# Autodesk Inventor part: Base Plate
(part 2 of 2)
node "Face6"
  sketch "Sketch28"
    geometry: L1 (-175.545, 291.309)-(-196.287, 260.747) reference; L2 (304.8, 342.9)-(304.8, 127) reference; L3 (-192.1, 280.581)-(-182.826, 280.581); L4 (-197.815, 271.464)-(-194.15, 263.894); L5 (-194.15, 263.894)-(-182.826, 280.581); L6 (-175.545, 123.828)-(-196.287, 93.265) reference; L7 (-118.712, 207.569)-(-139.454, 177.006) reference; L8 (-139.454, 241.697)-(-118.712, 211.135) reference; L9 (-118.712, 291.309)-(-139.454, 260.747) reference; L10 (-173.125, 135.136)-(-193.867, 165.698) reference; L11 (-193.867, 169.264)-(-173.125, 199.827) reference; L12 (-116.292, 135.136)-(-137.034, 165.698) reference; L13 (-137.034, 253.005)-(-116.292, 283.567) reference; L14 (-116.292, 302.617)-(-131.042, 324.351) reference; L15 (-128.415, 329.309)-(-98.915, 329.309) reference; L16 (-123.52, 313.267)-(-126.895, 318.24); L17 (-121.187, 276.355)-(-123.686, 265.644); L18 (-126.789, 279.408)-(-134.435, 271.502); L19 (-138.238, 262.538)-(-135.85, 269.224); L20 (-133.827, 257.73)-(-126.85, 261.501); L21 (-138.238, 262.538)-(-133.827, 257.73); L22 (-121.187, 276.355)-(-126.789, 279.408); L23 (-192.094, 211.118)-(-175.545, 211.135); L24 (-175.545, 211.135)-(-198.45, 244.885); L25 (-135.585, 213.092)-(-129.113, 226.46); L26 (-131.955, 204.327)-(-123.02, 201.221); L27 (-129.113, 226.46)-(-118.712, 211.135); L28 (-118.712, 207.569)-(-123.02, 201.221); L29 (-185.881, 161.988)-(-183.496, 150.417); L30 (-188.534, 165.96)-(-193.72, 169.48); L31 (-123.566, 154.323)-(-122.322, 144.02); L32 (-126.832, 159.138)-(-135.956, 164.11); L33 (-192.193, 110.292)-(-184.656, 110.402); L34 (116.292, 116.086)-(136.897, 85.725) reference; L35 (-193.867, 165.698)-(-183.496, 150.417); L36 (-196.287, 241.697)-(-175.545, 211.135) reference; L37 (-197.815, 220.236)-(-191.114, 234.076); L38 (-201.541, 93.265)-(-222.283, 123.828) reference; L39 (-203.543, 96.215)-(-201.541, 93.265); L40 (-196.287, 93.265)-(-184.656, 110.402); L41 (-123.52, 329.309)-(-123.52, 323.85); L42 (-197.815, 101.176)-(-194.944, 95.245); L43 (-123.52, 329.309)-(-126.626, 329.309); C1 r 1.905 at (-192.1, 274.231) reference; C2 r 1.905 at (-129.87, 323.85) reference; C3 r 1.905 at (-129.87, 267.087) reference; C4 r 1.905 at (-192.1, 217.468) reference; C5 r 1.905 at (-129.87, 210.325) reference; C6 r 1.905 at (-192.1, 160.706) reference; C7 r 1.905 at (-129.87, 153.562) reference; C8 r 1.905 at (-192.1, 103.943) reference; A1 r 6.35 centre (-129.87, 323.85) between (-126.895, 318.24) and (-123.52, 323.85); A2 r 6.35 centre (-192.1, 274.231) between (-192.1, 280.581) and (-197.815, 271.464); A3 r 3.175 centre (-178.172, 209.352) between (-175.545, 207.569) and (-175.545, 211.135) reference; A4 r 3.175 centre (-121.339, 209.352) between (-118.712, 207.569) and (-118.712, 211.135) reference; A5 r 6.35 centre (-129.87, 267.087) between (-123.686, 265.644) and (-134.435, 271.502); A6 r 6.35 centre (-192.1, 217.468) between (-198.45, 217.468) and (-192.094, 211.118); A7 r 6.35 centre (-129.87, 210.325) between (-135.585, 213.092) and (-131.955, 204.327); A8 r 3.175 centre (-121.339, 209.352) between (-118.712, 207.569) and (-118.712, 211.135); A9 r 6.35 centre (-192.1, 160.706) between (-185.881, 161.988) and (-188.534, 165.96); A10 r 6.35 centre (-129.87, 153.562) between (-123.566, 154.323) and (-126.832, 159.138); A11 r 6.35 centre (-192.1, 103.943) between (-198.098, 106.028) and (-192.193, 110.292); A12 r 3.175 centre (-191.239, 167.481) between (-193.867, 169.264) and (-193.867, 165.698) reference; A13 r 3.19 centre (-191.227, 167.49) between (-193.72, 169.48) and (-193.867, 165.698); A14 r 3.175 centre (-198.914, 95.048) between (-201.541, 93.265) and (-196.287, 93.265) reference; A15 r 3.175 centre (-198.914, 95.048) between (-201.541, 93.265) and (-196.287, 93.265); 5 further points
    constraints: 56 end point, 30 tangent, 29 point on circle, 19 point on line, 11 centre point, 8 coincident, 4 collinear, 3 parallel, 2 perpendicular, 1 midpoint, 1 vertical
    dimensions: "d254" = 12.7 diameter of A2; "d260" = 12.7 diameter of A5; "d261" = 12.7 distance of L17.start A5.centre; "d262" = 12.7 distance of L18.start C3.centre; "d263" = 9.525 distance of C3.centre L19.start; "d264" = 10.16 distance of C3.centre L20.start; "d265" = 12.7 diameter of A6; "d266" = 12.7 diameter of A7; "d267" = 12.7 diameter of A9; "d268" = 12.7 diameter of A10; "d269" = 12.1666 distance of L31.end C7.centre; "d270" = 12.7 diameter of A11; "d271" = 60 deg angle of L27 L25; "d272" = 75 deg angle of L7 L26; "d273" = 60 deg angle of L36 L37; "d274" = 60 deg angle of L1 L4; "d287" = 12.7 diameter of A1; "d288" = 60 deg angle of L6 L42; "d289" = 125 deg angle of L6 L33
sketch "Sketch29"
  geometry: C1 r 1.905 at (-192.1, 103.943) reference; C2 r 1.905 at (-129.87, 210.325) reference; C3 r 1.905 at (-192.1, 217.468) reference; C4 r 1.905 at (-192.1, 274.231) reference; A1 r 1.905 centre (-192.1, 160.706) between (-190.231, 160.341) and (-191.749, 162.578) reference; A2 r 1.905 centre (-129.87, 323.85) between (-129.442, 321.994) and (-131.383, 325.007) reference; A3 r 6.35 centre (-129.87, 153.562) between (-123.566, 154.323) and (-126.832, 159.138) reference; A4 r 6.35 centre (-129.87, 267.087) between (-126.85, 261.501) and (-123.686, 265.644) reference; 1 further point
hole "Hole2" sketch "Sketch29" at (-129.87, 323.85), (-192.1, 274.231), (-129.87, 267.087), (-192.1, 217.468), (-129.87, 210.325), (-192.1, 160.706), (-129.87, 153.562), (-192.1, 103.943) diameter "d280" = 3.81; stored, may be unused: countersink angle "d284" = 82 deg, drill point angle "d286" = 118 deg; dims "d281" = 19.05, "d282" = 9.525, "d283" = 6.35, "d285" = 3.175 (derived)
pattern_linear "Rectangular Pattern17" dims "d294" = 340.995
node "Face9"
  sketch "Sketch37"
    geometry: L1 (-285.75, -236.538)-(-285.75, -258.763) reference; L2 (-288.925, -236.538)-(-288.925, -258.763); L3 (-285.75, -185.738)-(-285.75, -207.963) reference; L4 (-128.415, 329.309)-(-98.915, 329.309) reference; L5 (-288.925, -207.963)-(-288.925, -185.738); A1 r 7.937 centre (-292.1, -222.25) between (-292.1, -214.313) and (-292.1, -230.188) reference; A2 r 6.35 centre (-292.1, -236.538) between (-285.75, -236.538) and (-292.1, -230.188) reference; A3 r 6.35 centre (-292.1, -258.763) between (-292.1, -265.113) and (-285.75, -258.763) reference; A4 r 7.937 centre (-292.1, -273.05) between (-292.1, -265.113) and (-297.713, -267.437) reference; A5 r 6.804 centre (-295.729, -236.538) between (-288.925, -236.538) and (-294.054, -229.943); A6 r 6.804 centre (-295.729, -258.763) between (-294.054, -265.357) and (-288.925, -258.763); A7 r 6.35 centre (-292.1, -185.738) between (-285.75, -185.738) and (-292.1, -179.388) reference; A8 r 6.35 centre (-292.1, -207.963) between (-292.1, -214.313) and (-285.75, -207.963) reference; A9 r 6.804 centre (-295.729, -207.963) between (-294.054, -214.557) and (-288.925, -207.963); A10 r 6.35 centre (-295.275, -185.738) between (-288.925, -185.738) and (-295.275, -179.388); 4 further points; 1 other entity
    constraints: 11 point on circle, 7 tangent, 4 centre point, 4 end point, 4 horizontal alignment, 2 parallel, 1 perpendicular, 3 other
    dimensions: "d319" = 3.175 distance between parallel lines of L1 L2; "d325" = 3.175 distance between parallel lines of L5 L3 (derived)
mirror "Mirror28"
mirror "Mirror29"
node "Face10"
sketch "Sketch39" dims "d528" = 25.4, "d529" = 25.4, "d530" = 25.4
  geometry: L1 (-175.545, 123.828)-(-196.287, 93.265); L2 (-195.275, 275.552)-(-195.275, 325.171) reference; L3 (-126.695, 325.171)-(-126.695, 275.552) reference; L4 (-188.131, 329.309)-(-196.069, 329.309); L5 (-196.069, 329.309)-(-196.069, 93.586); L6 (-196.069, 93.586)-(-188.131, 93.586); L7 (-188.131, 93.586)-(-188.131, 329.309); L8 (-126.298, 92.161)-(-133.442, 92.161); L9 (-133.442, 92.161)-(-133.442, 329.309); L10 (-133.442, 329.309)-(-126.298, 329.309); L11 (-126.298, 329.309)-(-126.298, 101.342); L12 (-195.275, 272.377)-(-195.275, 321.996) reference; L13 (-126.298, 92.161)-(-126.298, 101.342); L14 (-193.73, 85.725)-(-147.265, 85.725); L15 (-128.415, 329.309)-(-98.915, 329.309); L16 (-90.487, 330.2)-(-112.712, 330.2) reference; L17 (-192.087, 330.2)-(-214.312, 330.2) reference; C1 r 1.905 at (-129.87, 318.821); C2 r 1.905 at (-129.87, 260.998); C3 r 1.905 at (-129.87, 203.175); C4 r 1.905 at (-129.87, 145.351); C5 r 1.905 at (-192.1, 318.821); C6 r 1.905 at (-192.1, 260.998); C7 r 1.905 at (-192.1, 203.175); C8 r 1.905 at (-192.1, 145.351); C9 r 1.905 at (-129.87, 95.733); C10 r 1.905 at (-192.1, 95.733); C11 r 1.905 at (-192.1, 153.556); C12 r 1.905 at (-129.87, 153.556); C13 r 1.905 at (-129.87, 211.379); C14 r 1.905 at (-192.1, 211.379); C15 r 1.905 at (-192.1, 269.202); C16 r 1.905 at (-129.87, 269.202); 22 further points
  constraints: 30 end point, 16 centre point, 5 vertical, 4 horizontal alignment, 4 parallel, 3 horizontal, 2 midpoint, 2 perpendicular, 1 collinear, 1 point on line, 1 vertical alignment, 36 other
  dimensions: "d517" = 7.14375 distance between parallel lines of L2 L7; "d518" = 7.14375 distance between parallel lines of L9 L11 (derived); "d519" = 0.79375 distance between parallel lines of L2 L5; "d520" = 0.39688 distance between parallel lines of L3 L11; "d521" = 10.4878 distance from line of L15 C1.centre; "d522" = 3.81 diameter of C1; "d523" = 57.8231 distance of C1.centre C2.centre; "d524" = 62.23 distance of C1.centre C5.centre; "d525" = 49.6189 distance of C4.centre C9.centre; "d526" = 3.57187 distance from line of C9.centre L8 (derived); "d527" = 3.57187 distance from line of L13 C9.centre (derived); "d531" = 11.3792 distance from line of L16 C1.centre; "d532" = 11.3792 distance from line of L17 C5.centre
hole "Hole5" sketch "Sketch39" at (-129.87, 153.556), (-129.87, 145.351), (-192.1, 153.556), (-192.1, 145.351), (-129.87, 95.733), (-192.1, 95.733), (-129.87, 318.821), (-192.1, 318.821), (-192.1, 269.202), (-129.87, 269.202), (-129.87, 260.998), (-192.1, 260.998)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 diameter "d342" = 3.81; stored, may be unused: countersink angle "d346" = 82 deg, drill point angle "d348" = 118 deg; dims "d343" = 19.05, "d344" = 9.525, "d345" = 6.35, "d347" = 3.175 (derived)
mirror "Mirror30"
node "Face11"
  sketch "Sketch40"
    geometry: L1 (-59.46, 302.617)-(-74.21, 324.351) reference; L2 (-71.583, 329.309)-(-42.082, 329.309) reference; L3 (196.287, 260.747)-(175.545, 291.309) reference; L4 (-69.85, 299.214)-(-57.15, 299.214); L5 (-57.15, 299.214)-(-57.15, 329.309); L6 (-57.15, 329.309)-(-69.85, 329.309); L7 (-69.85, 329.309)-(-69.85, 299.214); L8 (-69.85, 317.927)-(-57.15, 299.214); L9 (-57.15, 299.214)-(-57.15, 299.214); L10 (196.069, 325.117)-(196.069, 261.067) reference; L11 (-69.85, 317.927)-(-74.21, 324.351); L12 (-69.85, 329.309)-(-71.583, 329.309); C1 r 3.264 at (-63.5, 313.552); A1 r 3.175 centre (-71.583, 326.134) between (-71.583, 329.309) and (-74.21, 324.351) reference; A2 r 3.175 centre (-71.583, 326.134) between (-71.583, 329.309) and (-74.21, 324.351); 3 further points
    constraints: 16 end point, 6 point on line, 4 tangent, 3 parallel, 2 centre point, 2 midpoint, 2 perpendicular, 2 point on circle, 1 horizontal, 1 vertical alignment
    dimensions: "d349" = 12.7 distance between parallel lines of L5 L7; "d437" = 15.75614 distance from line of L6 C1.centre; "d438" = 6.5278 diameter of C1
node "Face12"
sketch "Sketch42"
  geometry: C1 r 3.264 at (-63.5, 110.352); C2 r 3.264 at (-63.5, 104.002); A1 r 3.264 centre (-63.5, 110.352) between (-65.229, 107.584) and (-61.566, 112.982) reference; 4 further points
  constraints: 2 centre point, 2 coincident, 1 concentric, 2 other
cut "Cut22" sketch "Sketch42" dims "d360" = 3.175 (derived), "d361" = 0
mirror "Mirror31"
node "Face13"
  sketch "Sketch43"
    geometry: L1 (-111.038, -218.876)-(-90.296, -249.439) reference; L2 (90.296, -249.439)-(111.038, -218.876) reference; L3 (-98.915, -329.309)-(-128.415, -329.309) reference; L4 (128.415, -329.309)-(98.915, -329.309) reference; L5 (-101.695, -329.309)-(-92.17, -329.309); L6 (-92.17, -329.309)-(-92.17, -238.887); L7 (-93.46, -229.362)-(-101.695, -229.362); L8 (-101.695, -229.362)-(-101.695, -329.309); L9 (-101.695, -229.362)-(101.695, -229.362); L10 (101.695, -229.362)-(101.695, -245.237); L11 (-101.695, -242.062)-(-101.695, -229.362); L12 (101.695, -229.362)-(91.525, -229.362); L13 (92.17, -238.887)-(92.17, -329.309); L14 (92.17, -329.309)-(101.695, -329.309); L15 (101.695, -329.309)-(101.695, -229.362); L16 (-101.695, -229.362)-(-101.695, -232.642); L17 (-101.695, -232.642)-(-103.922, -229.362); L18 (101.695, -229.362)-(101.695, -232.642); L19 (101.695, -232.642)-(103.922, -229.362); L20 (-90.296, -253.005)-(-111.038, -283.567) reference; L21 (111.038, -283.567)-(90.296, -253.005) reference; L22 (82.622, 93.265)-(71.943, 109) reference; L23 (-92.17, -255.767)-(-89.086, -251.222); L24 (-92.17, -246.677)-(-89.086, -251.222); L25 (92.17, -246.677)-(89.086, -251.222); L26 (92.17, -255.767)-(89.086, -251.222); L27 (14.75, -329.309)-(-14.75, -329.309) reference; L28 (87.876, 157.956)-(108.618, 127.394) reference; L29 (-92.17, -260.747)-(-76.2, -238.887); L30 (-76.2, -238.887)-(-92.17, -238.887); L31 (-92.17, -260.747)-(-92.17, -238.887); L32 (-36.091, -238.887)-(-28.929, -249.439); L33 (-28.929, -249.439)-(-21.22, -238.887); L34 (19.574, -238.887)-(26.736, -249.439); L35 (26.736, -249.439)-(35.197, -238.887); L36 (19.574, -238.887)-(35.197, -238.887); L37 (-36.091, -238.887)-(-21.22, -238.887); L38 (92.17, -260.747)-(77.335, -238.887); L39 (77.335, -238.887)-(92.17, -238.887); L40 (92.17, -238.887)-(92.17, -260.747); C1 r 2.489 at (-46.133, -234.124); C2 r 2.489 at (46.133, -234.124); C3 r 2.489 at (96.933, -234.124); C4 r 2.489 at (-96.933, -285.337); C5 r 2.489 at (96.933, -285.337); C6 r 2.489 at (-96.933, -285.337); C7 r 2.489 at (-96.933, -234.124); 14 further points
    constraints: 62 end point, 18 point on line, 13 parallel, 7 centre point, 6 horizontal, 4 perpendicular, 3 collinear, 3 horizontal alignment, 3 midpoint, 3 vertical alignment, 1 coincident, 1 concentric, 1 vertical, 17 other
    dimensions: "d362" = 9.525 distance between parallel lines of L6 L8; "d364" = 9.525 dimension on L9; "d365" = 4.7625 distance from line of L10 C3.centre; "d366" = 9.525 distance between parallel lines of L15 L13 (derived); "d448" = 4.9784 diameter of C4; "d450" = 4.9784 diameter of C1 (derived); "d451" = 92.2655 distance of C2.centre C1.centre; "d452" = 4.9784 diameter of C2 (derived); "d454" = 4.9784 diameter of C3 (derived); "d455" = 4.9784 diameter of C5 (derived); "d458" = 4.9784 diameter of C7 (derived); "d459" = 95.1841 distance from line of L3 C7.centre; "d460" = 4.7625 distance from line of L7 C7.centre; "d461" = 51.21275 distance of C3.centre C5.centre; "d462" = 51.21275 distance of C7.centre C4.centre (derived); "d463" = 4.7625 distance from line of L8 C7.centre; "d464" = 50.8 distance of C7.centre C1.centre; "d467" = 50.8 distance of C3.centre C2.centre
sketch "Sketch44"
  geometry: C1 r 2.489 at (46.133, -234.124) reference; C2 r 2.489 at (96.933, -285.337) reference; C3 r 2.489 at (-46.133, -234.124) reference; C4 r 2.489 at (-96.933, -285.337) reference; C5 r 2.489 at (-46.133, -240.475) reference; C6 r 2.489 at (46.133, -240.475) reference; C7 r 2.489 at (-96.933, -291.687) reference; C8 r 2.489 at (96.933, -291.687) reference; C9 r 3.264 at (-63.5, 104.002); C10 r 2.489 at (96.933, -234.124); C11 r 2.489 at (-96.933, -234.124); A1 r 2.489 centre (-96.933, -237.3) between (-99.213, -236.3) and (-96.846, -239.787) reference; 5 further points
  constraints: 7 centre point, 2 horizontal alignment, 2 vertical alignment, 1 coincident, 10 other
  dimensions: "d468" = 4.9784 diameter of C10; "d471" = 4.9784 diameter of C11
cut "Cut23" sketch "Sketch44" dims "d373" = 3.175 (derived), "d374" = 0
node "Face14"
  sketch "Sketch45"
    geometry: L1 (25.789, 9.525)-(5.047, 40.087) reference; L2 (23.369, -169.264)-(2.627, -199.827) reference; L3 (-80.202, -249.439)-(-59.46, -218.876) reference; L4 (1.295, -201.219)-(13.995, -201.219); L5 (13.995, -201.219)-(13.995, 36.259); L6 (13.995, 36.259)-(1.295, 36.259); L7 (1.295, 36.259)-(1.295, -201.219); L8 (13.995, 26.903)-(7.645, 36.259); L9 (7.645, 36.259)-(1.295, 36.259); L10 (13.995, -183.076)-(1.682, -201.219); C1 r 2.847 at (7.645, -19.7) reference; C2 r 2.665 at (7.635, -19.698) reference; C3 r 2.665 at (7.635, -184.798) reference; A1 r 3.175 centre (0, -198.044) between (-2.627, -199.827) and (2.627, -199.827) reference; 2 further points
    constraints: 14 end point, 5 point on line, 3 centre point, 3 parallel, 2 collinear, 1 horizontal, 1 midpoint, 1 perpendicular, 1 tangent, 1 vertical alignment, 6 other
    dimensions: "d375" = 12.7 distance between parallel lines of L5 L7
node "Face15"
  sketch "Sketch46"
    geometry: L1 (118.712, -207.569)-(139.454, -177.006) reference; L2 (201.541, -93.265)-(222.283, -123.828) reference; L3 (-54.205, -218.876)-(-33.463, -249.439) reference; L4 (108.28, -133.744)-(117.805, -133.744); L5 (117.805, -133.744)-(117.805, -166.663); L6 (117.805, -176.188)-(108.28, -176.188); L7 (108.28, -176.188)-(108.28, -133.744); L8 (108.28, -176.188)-(140.01, -176.188); L9 (140.01, -176.188)-(140.01, -166.663); L10 (140.01, -166.663)-(117.805, -166.663); L11 (108.28, -166.663)-(108.28, -176.188); L12 (232.105, -117.478)-(232.105, -103.163); L13 (232.105, -103.163)-(208.258, -103.163); L14 (208.258, -103.163)-(217.973, -117.478); L15 (217.973, -117.478)-(232.105, -117.478); C1 r 2.265 at (113.042, -171.425) reference; C2 r 2.265 at (227.342, -107.925) reference; A1 r 3.175 centre (113.665, -136.919) between (116.292, -135.136) and (111.038, -135.136) reference; A2 r 3.175 centre (227.33, -114.303) between (224.703, -116.086) and (229.957, -116.086) reference; 3 further points
    constraints: 24 end point, 6 parallel, 3 horizontal, 3 perpendicular, 2 centre point, 2 tangent, 1 collinear, 1 midpoint, 1 point on line, 1 vertical alignment, 4 other
    dimensions: "d381" = 9.525 distance between parallel lines of L5 L7; "d382" = 4.7625 distance from line of C1.centre L6; "d383" = 9.525 distance between parallel lines of L10 L8; "d384" = 4.7625 distance from line of L7 C1.centre; "d385" = 4.7625 distance from line of L12 C2.centre; "d386" = 4.7625 distance from line of L13 C2.centre
feature "Corner Round19" dims "d392" = 3.175
node "Face16"
  sketch "Sketch47"
    geometry: L1 (147.701, -284.48)-(191.643, -284.48); L2 (191.643, -284.48)-(191.643, -270.51); L3 (191.643, -270.51)-(147.701, -270.51); L4 (147.701, -270.51)-(147.701, -284.48); L5 (147.701, -284.48)-(191.643, -270.51); L6 (191.643, -284.48)-(147.701, -270.51); L7 (135.001, -297.18)-(204.343, -297.18); L8 (204.343, -297.18)-(204.343, -257.81); L9 (204.343, -257.81)-(135.001, -257.81); L10 (135.001, -257.81)-(135.001, -297.18); L11 (135.001, -297.18)-(204.343, -257.81); L12 (204.343, -297.18)-(135.001, -257.81); C1 r 3.302 at (141.351, -290.83) reference; C2 r 3.302 at (197.993, -264.16) reference; 3 further points
    constraints: 24 end point, 5 midpoint, 4 parallel, 2 centre point, 2 horizontal, 2 perpendicular, 4 other
    dimensions: "d393" = 6.35 distance from line of L8 C2.centre; "d394" = 6.35 distance from line of C2.centre L2 (derived); "d395" = 6.35 distance from line of L1 C1.centre (derived); "d396" = 6.35 distance from line of L10 C1.centre (derived); "d397" = 12.7 distance between parallel lines of L9 L3; "d398" = 6.35 distance from line of L9 C2.centre
feature "Corner Round20" dims "d404" = 3.175
node "Face17"
  sketch "Sketch49"
    geometry: L1 (111.038, -199.827)-(90.296, -169.264) reference; L2 (108.28, -173.013)-(108.28, -139.2) reference; L3 (-183.203, -232.719)-(-183.203, -274.371); L4 (-183.203, -274.371)-(-170.498, -293.092); L5 (-170.498, -293.092)-(-157.803, -270.506); L6 (-157.803, -270.506)-(-157.803, -232.719); L7 (-157.803, -232.719)-(-171.697, -212.247); L8 (-171.697, -212.247)-(-183.203, -232.719); C1 r 3.175 at (-171.697, -231.642) reference; C2 r 3.175 at (-171.697, -268.542) reference; 1 further point
    constraints: 12 end point, 5 parallel, 2 centre point, 1 horizontal alignment, 1 vertical alignment, 4 other
    dimensions: "d408" = 11.5062 distance from line of L3 C2.centre; "d409" = 13.8938 distance from line of C2.centre L6
node "Face18"
  sketch "Sketch50"
    geometry: L1 (87.876, -177.006)-(108.618, -207.569) reference; L2 (203.961, -165.698)-(224.703, -135.136) reference; L3 (229.957, -135.136)-(250.699, -165.698) reference; L4 (242.08, -329.309)-(212.58, -329.309) reference; L5 (196.287, -325.438)-(177.109, -297.18) reference; L6 (108.28, -138.174)-(232.105, -138.174); L7 (232.105, -138.174)-(232.105, -211.199); L8 (232.105, -211.199)-(108.28, -211.199); L9 (108.28, -211.199)-(108.28, -138.174); L10 (216.177, -147.699)-(238.483, -147.699); L11 (238.483, -147.699)-(229.957, -135.136); L12 (224.703, -135.136)-(216.177, -147.699); L13 (108.618, -207.569)-(108.28, -207.071); L14 (108.28, -211.199)-(117.805, -211.199); L15 (117.805, -211.199)-(117.805, -201.674); L16 (117.805, -201.674)-(108.28, -201.674); L17 (108.28, -201.674)-(108.28, -211.199); L18 (108.618, -211.135)-(96.247, -229.362) reference; L19 (222.283, -294.875)-(201.541, -325.438) reference; L20 (177.109, -297.18)-(201.168, -297.18) reference; L21 (108.28, -211.199)-(108.28, -211.632); L22 (108.28, -211.632)-(108.618, -211.135); C1 r 2.265 at (113.042, -171.425) reference; C2 r 2.265 at (113.042, -206.436); C3 r 2.265 at (227.342, -142.936); A1 r 3.175 centre (105.991, -209.352) between (108.618, -211.135) and (108.618, -207.569) reference; A2 r 3.175 centre (227.33, -136.919) between (229.957, -135.136) and (224.703, -135.136) reference; A3 r 3.175 centre (227.33, -136.919) between (229.957, -135.136) and (224.703, -135.136); A4 r 3.175 centre (105.991, -209.352) between (108.618, -211.135) and (108.618, -207.569); 2 further points
    constraints: 28 end point, 9 tangent, 6 parallel, 5 point on line, 4 centre point, 4 perpendicular, 4 point on circle, 2 horizontal, 1 collinear, 1 vertical alignment
    dimensions: "d415" = 123.825 distance between parallel lines of L7 L9; "d416" = 4.7625 distance from line of L9 C2.centre; "d417" = 4.7625 distance from line of L8 C2.centre; "d418" = 73.025 distance between parallel lines of L6 L8; "d419" = 118.11 distance between parallel lines of L4 L8; "d420" = 4.53099 diameter of C2; "d421" = 4.53099 diameter of C3; "d422" = 4.7625 distance from line of L7 C3.centre; "d423" = 4.7625 distance from line of L6 C3.centre; "d424" = 9.525 distance between parallel lines of L6 L10; "d425" = 9.525 distance of L16.end L15.end; "d426" = 9.525 distance between parallel lines of L14 L16
sketch "Sketch51"
  geometry: C1 r 2.265 at (227.342, -142.936) reference; C2 r 2.265 at (113.042, -206.436); 1 further point
  constraints: 1 centre point
  dimensions: "d432" = 4.53099 diameter of C2; "d433" = 63.5 vertical distance of C1.centre C2.centre; "d434" = 114.3 horizontal distance of C1.centre C2.centre
cut "Cut24" sketch "Sketch51" dims "d435" = 3.175 (derived), "d436" = 0
feature "Corner Round21" dims "d443" = 6.35
feature "Corner Round22" dims "d444" = 3.175
feature "Corner Round23" dims "d445" = 6.35
feature "Corner Round24" dims "d446" = 3.175
feature "Corner Round25" dims "d457" = 3.175
feature "Corner Round26" dims "d472" = 25.4
sketch "Sketch52"
  geometry: A1 r 3.264 centre (63.5, 313.552) between (66.759, 313.372) and (64.871, 310.59) reference; A2 r 3.264 centre (-63.5, 313.552) between (-64.871, 310.59) and (-66.759, 313.372) reference; 1 further point
hole "Hole6" sketch "Sketch52" at (-63.5, 313.552), (63.5, 313.552) diameter "d541" = 6.5278; stored, may be unused: countersink angle "d545" = 82 deg, drill point angle "d547" = 118 deg; dims "d542" = 19.05, "d543" = 9.525, "d544" = 6.35, "d546" = 3.175 (derived)
node "Face19"
  sketch "Sketch53"
    geometry: L1 (-14.75, 329.309)-(14.75, 329.309) reference; L2 (11.112, 330.2)-(-11.112, 330.2) reference; L3 (-129.473, 92.161)-(-132.53, 92.161) reference; L4 (13.304, 335.659)-(-13.304, 335.659); A1 r 7.938 centre (25.4, 336.55) between (33.337, 336.55) and (17.462, 336.55) reference; A2 r 6.35 centre (11.112, 336.55) between (11.112, 330.2) and (17.462, 336.55) reference; A3 r 6.35 centre (-11.112, 336.55) between (-17.462, 336.55) and (-11.112, 330.2) reference; A4 r 7.938 centre (-25.4, 336.55) between (-17.462, 336.55) and (-33.337, 336.55) reference; A5 r 4.763 centre (-13.304, 340.421) between (-17.84, 338.969) and (-13.304, 335.659); A6 r 4.763 centre (13.304, 340.421) between (13.304, 335.659) and (17.84, 338.969); 1 further point
    constraints: 6 point on circle, 4 tangent, 2 centre point, 2 end point, 1 parallel
    dimensions: "d549" = 6.35 distance between parallel lines of L4 L1; "d550" = 4.7625 radius of A5; "d551" = 4.7625 radius of A6 (derived)
mirror "Mirror32"
sketch "Sketch54"
  geometry: L1 (126.298, 317.361)-(116.292, 302.617) reference; L2 (111.038, 302.617)-(96.288, 324.351) reference; L3 (98.915, 329.309)-(126.298, 329.309) reference; L4 (126.298, 329.309)-(126.298, 317.361) reference; L5 (-88.352, 73.514)-(-87.876, 74.216) reference; L6 (-82.622, 74.216)-(-61.88, 43.653) reference; L7 (-61.88, 40.087)-(-82.622, 9.525) reference; L8 (-87.876, 9.525)-(-88.352, 10.227) reference; L9 (-88.9, 71.731)-(-88.9, 12.01) reference; L10 (54.205, 218.876)-(33.463, 249.439) reference; L11 (33.463, 253.005)-(54.205, 283.567) reference; L12 (59.46, 283.567)-(80.202, 253.005) reference; L13 (80.202, 249.439)-(59.46, 218.876) reference; L14 (-2.627, 135.136)-(-23.369, 165.698) reference; L15 (-23.369, 169.264)-(-2.627, 199.827) reference; L16 (2.627, 199.827)-(23.369, 169.264) reference; L17 (23.369, 165.698)-(2.627, 135.136) reference; L18 (108.618, 291.309)-(87.876, 260.747) reference; L19 (82.622, 260.747)-(61.88, 291.309) reference; L20 (61.88, 294.875)-(82.622, 325.438) reference; L21 (87.876, 325.438)-(108.618, 294.875) reference; L22 (51.785, 207.569)-(31.043, 177.006) reference; L23 (25.789, 177.006)-(5.047, 207.569) reference; L24 (5.047, 211.135)-(25.789, 241.697) reference; L25 (31.043, 241.697)-(51.785, 211.135) reference; L26 (-5.047, 123.828)-(-25.789, 93.265) reference; L27 (-31.043, 93.265)-(-51.785, 123.828) reference; L28 (-51.785, 127.394)-(-31.043, 157.956) reference; L29 (-25.789, 157.956)-(-5.047, 127.394) reference; L30 (-64.017, 95.559)-(-40.274, 95.559) reference; L31 (-40.274, 95.559)-(-33.463, 85.524) reference; L32 (-33.463, 81.958)-(-54.205, 51.395) reference; L33 (-59.46, 51.395)-(-80.202, 81.958) reference; L34 (-80.202, 85.524)-(-70.798, 99.379) reference; A1 r 3.175 centre (113.665, 304.4) between (111.038, 302.617) and (116.292, 302.617) reference; A2 r 3.175 centre (98.915, 326.134) between (98.915, 329.309) and (96.288, 324.351) reference; A3 r 3.175 centre (-85.249, 72.433) between (-82.622, 74.216) and (-87.876, 74.216) reference; A4 r 3.175 centre (-64.507, 41.87) between (-61.88, 40.087) and (-61.88, 43.653) reference; A5 r 3.175 centre (-85.249, 11.308) between (-87.876, 9.525) and (-82.622, 9.525) reference; A6 r 3.175 centre (-85.725, 12.01) between (-88.9, 12.01) and (-88.352, 10.227) reference; A7 r 3.175 centre (-85.725, 71.731) between (-88.352, 73.514) and (-88.9, 71.731) reference; A8 r 3.175 centre (36.091, 251.222) between (33.463, 253.005) and (33.463, 249.439) reference; A9 r 3.175 centre (56.832, 281.784) between (59.46, 283.567) and (54.205, 283.567) reference; A10 r 3.175 centre (77.574, 251.222) between (80.202, 249.439) and (80.202, 253.005) reference; A11 r 3.175 centre (56.832, 220.659) between (54.205, 218.876) and (59.46, 218.876) reference; A12 r 3.175 centre (-20.742, 167.481) between (-23.369, 169.264) and (-23.369, 165.698) reference; A13 r 3.175 centre (0, 198.044) between (2.627, 199.827) and (-2.627, 199.827) reference; A14 r 3.175 centre (20.742, 167.481) between (23.369, 165.698) and (23.369, 169.264) reference; A15 r 3.175 centre (0, 136.919) between (-2.627, 135.136) and (2.627, 135.136) reference; A16 r 3.175 centre (85.249, 262.53) between (82.622, 260.747) and (87.876, 260.747) reference; A17 r 3.175 centre (64.507, 293.092) between (61.88, 294.875) and (61.88, 291.309) reference; A18 r 3.175 centre (85.249, 323.655) between (87.876, 325.438) and (82.622, 325.438) reference; A19 r 3.175 centre (105.991, 293.092) between (108.618, 291.309) and (108.618, 294.875) reference; A20 r 3.175 centre (28.416, 178.789) between (25.789, 177.006) and (31.043, 177.006) reference; A21 r 3.175 centre (7.674, 209.352) between (5.047, 211.135) and (5.047, 207.569) reference; A22 r 3.175 centre (28.416, 239.914) between (31.043, 241.697) and (25.789, 241.697) reference; A23 r 3.175 centre (49.158, 209.352) between (51.785, 207.569) and (51.785, 211.135) reference; A24 r 3.175 centre (-28.416, 95.048) between (-31.043, 93.265) and (-25.789, 93.265) reference; A25 r 3.175 centre (-49.158, 125.611) between (-51.785, 127.394) and (-51.785, 123.828) reference; A26 r 3.175 centre (-28.416, 156.173) between (-25.789, 157.956) and (-31.043, 157.956) reference; A27 r 3.175 centre (-7.674, 125.611) between (-5.047, 123.828) and (-5.047, 127.394) reference; A28 r 3.175 centre (-36.091, 83.741) between (-33.463, 81.958) and (-33.463, 85.524) reference; A29 r 3.175 centre (-56.833, 53.178) between (-59.46, 51.395) and (-54.205, 51.395) reference; A30 r 3.175 centre (-77.574, 83.741) between (-80.202, 85.524) and (-80.202, 81.958) reference; 2 further points; 1 other entity
  constraints: 1 other
cut "Cut25" sketch "Sketch54" dims "d563" = 3.175 (derived), "d564" = 0
body "Solid1"
pattern_linear "Rectangular Pattern1" dims "d10" = 12.7
pattern_linear "Rectangular Pattern2" dims "d16" = 12.7
pattern_linear "Rectangular Pattern5" dims "d71" = 88.99079, "d74" = 88.99079
pattern_linear "Rectangular Pattern18" dims "d559" = 50.8, "d562" = 50.8
face "Plate1" dims "Thickness" = 3.175 (derived)
face "Plate2" dims "d192" = 3.175 (derived), "d193" = 3.175 (derived), "d195" = 6.35 (derived), "Thickness" = 3.175 (derived)
bend "Bend1" dims "d192" = 3.175 (derived), "d193" = 3.175 (derived), "d194" = 1.5875 (derived), "d195" = 6.35 (derived), "d196" = 3.175 (derived), "SeamGap" = 0.00508, "Thickness" = 3.175 (derived)
sketch "Sketch22"
  geometry: L1 (-355.6, 114.3)-(-355.6, 101.6) reference; C1 r 2.489 at (-285.75, 114.3); C2 r 2.489 at (-304.8, 107.95); C3 r 2.489 at (-292.1, 107.95) reference; 4 further points
  constraints: 2 centre point, 1 horizontal alignment, 1 midpoint
  dimensions: "d235" = 4.9784 diameter of C2; "d326" = 12.7 distance of C3.centre C2.centre
face "Plate3" dims "d219" = 3.175 (derived), "d220" = 3.175 (derived), "d222" = 6.35 (derived), "Thickness" = 3.175 (derived)
bend "Bend2" dims "d219" = 3.175 (derived), "d220" = 3.175 (derived), "d221" = 1.5875 (derived), "d222" = 6.35 (derived), "d223" = 3.175 (derived), "SeamGap" = 0.00508, "Thickness" = 3.175 (derived)
face "Plate4" dims "d245" = 3.175 (derived), "d246" = 3.175 (derived), "d248" = 6.35 (derived), "Thickness" = 3.175 (derived)
bend "Bend3" dims "d245" = 3.175 (derived), "d246" = 3.175 (derived), "d247" = 1.5875 (derived), "d248" = 6.35 (derived), "d249" = 3.175 (derived), "SeamGap" = 0.00508, "Thickness" = 3.175 (derived)
node "Reference2"
node "Reference3"
node "Reference4"
node "Reference5"
node "Reference6"
node "Reference7"
node "Reference8"
node "Reference9"
face "Plate6" dims "d275" = 3.175 (derived), "d276" = 3.175 (derived), "d278" = 6.35 (derived), "Thickness" = 3.175 (derived)
bend "Bend5" dims "d275" = 3.175 (derived), "d276" = 3.175 (derived), "d277" = 1.5875 (derived), "d278" = 6.35 (derived), "d279" = 3.175 (derived), "SeamGap" = 0.00508, "Thickness" = 3.175 (derived)
face "Plate9" dims "d320" = 3.175 (derived), "d321" = 3.175 (derived), "d323" = 6.35 (derived), "Thickness" = 3.175 (derived)
bend "Bend8" dims "d320" = 3.175 (derived), "d321" = 3.175 (derived), "d322" = 1.5875 (derived), "d323" = 6.35 (derived), "d324" = 3.175 (derived), "SeamGap" = 0.00508, "Thickness" = 3.175 (derived)
sketch "Sketch38" dims "d487" = 25.4, "d494" = 25.4, "d501" = 25.4
  geometry: L1 (-175.545, 123.828)-(-196.287, 93.265) reference; L2 (-195.275, 275.552)-(-195.275, 325.171) reference; L3 (-126.695, 325.171)-(-126.695, 275.552) reference; L4 (-188.131, 329.309)-(-196.069, 329.309); L5 (-196.069, 329.309)-(-196.069, 93.586); L6 (-196.069, 93.586)-(-188.131, 93.586); L7 (-188.131, 93.586)-(-188.131, 329.309); L8 (-126.298, 92.161)-(-133.442, 92.161); L9 (-133.442, 92.161)-(-133.442, 329.309); L10 (-133.442, 329.309)-(-126.298, 329.309); L11 (-126.298, 329.309)-(-126.298, 101.342); L12 (-195.275, 272.377)-(-195.275, 321.996) reference; L13 (-126.298, 92.161)-(-126.298, 101.342); L14 (-193.73, 85.725)-(-147.265, 85.725) reference; L15 (-128.415, 329.309)-(-98.915, 329.309) reference; C1 r 1.905 at (-129.87, 318.821); C2 r 1.905 at (-129.87, 260.998); C3 r 1.905 at (-129.87, 203.175); C4 r 1.905 at (-129.87, 145.351); C5 r 1.905 at (-192.1, 318.821); C6 r 1.905 at (-192.1, 260.998); C7 r 1.905 at (-192.1, 203.175); C8 r 1.905 at (-192.1, 145.351); C9 r 1.905 at (-129.87, 95.733); C10 r 1.905 at (-192.1, 95.733); C11 r 1.905 at (-192.1, 153.556); C12 r 1.905 at (-129.87, 153.556); C13 r 1.905 at (-129.87, 211.379); C14 r 1.905 at (-192.1, 211.379); C15 r 1.905 at (-192.1, 269.202); C16 r 1.905 at (-129.87, 269.202); 4 further points
  constraints: 24 end point, 16 centre point, 5 vertical, 4 parallel, 3 horizontal, 2 horizontal alignment, 2 midpoint, 2 perpendicular, 1 collinear, 1 point on line, 1 vertical alignment, 36 other
  dimensions: "d327" = 7.14375 distance between parallel lines of L2 L7; "d328" = 7.14375 distance between parallel lines of L9 L11 (derived); "d439" = 0.79375 distance between parallel lines of L2 L5; "d440" = 0.39688 distance between parallel lines of L3 L11; "d480" = 10.4878 distance from line of L15 C1.centre; "d481" = 3.81 diameter of C1; "d484" = 57.8231 distance of C1.centre C2.centre; "d491" = 62.23 distance of C1.centre C5.centre; "d498" = 49.6189 distance of C4.centre C9.centre; "d503" = 3.57187 distance from line of C9.centre L8 (derived); "d504" = 3.57187 distance from line of L13 C9.centre (derived)
face "Plate10" dims "d329" = 3.175 (derived), "d330" = 3.175 (derived), "d332" = 6.35 (derived), "Thickness" = 3.175 (derived)
bend "Bend9" dims "d329" = 3.175 (derived), "d330" = 3.175 (derived), "d331" = 1.5875 (derived), "d332" = 6.35 (derived), "d333" = 3.175 (derived), "SeamGap" = 0.00508, "Thickness" = 3.175 (derived)
face "Plate11" dims "d350" = 3.175 (derived), "d351" = 3.175 (derived), "d353" = 6.35 (derived), "Thickness" = 3.175 (derived)
bend "Bend10" dims "d350" = 3.175 (derived), "d351" = 3.175 (derived), "d352" = 1.5875 (derived), "d353" = 6.35 (derived), "d354" = 3.175 (derived), "SeamGap" = 0.00508, "Thickness" = 3.175 (derived)
sketch "Sketch41"
  geometry: L1 (-82.622, 157.956)-(-61.88, 127.394) reference; L2 (-54.205, 116.086)-(-33.463, 85.524); L3 (-71.943, 133.817)-(-71.943, 142.222); L4 (-71.943, 142.222)-(-44.584, 101.909); L5 (-71.943, 130.642)-(-71.943, 106.661); L6 (-64.017, 98.734)-(64.017, 98.734); L7 (-44.584, 101.909)-(-42.429, 98.734); L8 (-42.429, 98.734)-(-64.017, 98.734); L9 (-71.943, 106.661)-(-71.943, 142.222); L10 (-71.943, 142.222)-(-42.429, 98.734); L11 (-71.943, 106.661)-(-71.943, 105.59); L12 (-64.017, 95.559)-(64.017, 95.559) reference; L13 (-71.943, 127.467)-(-71.943, 103.486) reference; L14 (-40.274, 95.559)-(-42.429, 98.734); L15 (136.897, 85.725)-(90.433, 85.725) reference; L16 (-64.017, 98.734)-(-42.429, 98.734); L17 (-71.943, 106.661)-(-71.943, 103.486); C1 r 3.264 at (-63.5, 104.002); A1 r 7.927 centre (-64.017, 106.661) between (-71.943, 106.661) and (-64.017, 98.734); A2 r 3.264 centre (-63.5, 313.552) between (-64.871, 310.59) and (-66.759, 313.372) reference; A3 r 7.927 centre (-64.017, 106.661) between (-71.943, 106.661) and (-64.017, 98.734); 3 further points; 2 other entities
  constraints: 30 end point, 6 point on line, 5 tangent, 4 point on circle, 4 vertical, 3 centre point, 2 collinear, 2 horizontal, 1 parallel, 1 vertical alignment, 19 other
  dimensions: "d538" = 209.55 distance of A2.centre C1.centre
face "Plate12" dims "d355" = 3.175 (derived), "d356" = 3.175 (derived), "d358" = 6.35 (derived), "Thickness" = 3.175 (derived)
bend "Bend11" dims "d355" = 3.175 (derived), "d356" = 3.175 (derived), "d357" = 1.5875 (derived), "d358" = 6.35 (derived), "d359" = 3.175 (derived), "SeamGap" = 0.00508, "Thickness" = 3.175 (derived)
face "Plate13" dims "d368" = 3.175 (derived), "d369" = 3.175 (derived), "d371" = 6.35 (derived), "Thickness" = 3.175 (derived)
bend "Bend12" dims "d368" = 3.175 (derived), "d369" = 3.175 (derived), "d370" = 1.5875 (derived), "d371" = 6.35 (derived), "d372" = 3.175 (derived), "SeamGap" = 0.00508, "Thickness" = 3.175 (derived)
face "Plate14" dims "d376" = 3.175 (derived), "d377" = 3.175 (derived), "d379" = 6.35 (derived), "Thickness" = 3.175 (derived)
bend "Bend13" dims "d376" = 3.175 (derived), "d377" = 3.175 (derived), "d378" = 1.5875 (derived), "d379" = 6.35 (derived), "d380" = 3.175 (derived), "SeamGap" = 0.00508, "Thickness" = 3.175 (derived)
face "Plate15" dims "d387" = 3.175 (derived), "d388" = 3.175 (derived), "d390" = 6.35 (derived), "Thickness" = 3.175 (derived)
bend "Bend14" dims "d387" = 3.175 (derived), "d388" = 3.175 (derived), "d389" = 1.5875 (derived), "d390" = 6.35 (derived), "d391" = 3.175 (derived), "SeamGap" = 0.00508, "Thickness" = 3.175 (derived)
face "Plate16" dims "d399" = 3.175 (derived), "d400" = 3.175 (derived), "d402" = 6.35 (derived), "Thickness" = 3.175 (derived)
bend "Bend15" dims "d399" = 3.175 (derived), "d400" = 3.175 (derived), "d401" = 1.5875 (derived), "d402" = 6.35 (derived), "d403" = 3.175 (derived), "SeamGap" = 0.00508, "Thickness" = 3.175 (derived)
face "Plate17" dims "d410" = 3.175 (derived), "d411" = 3.175 (derived), "d413" = 6.35 (derived), "Thickness" = 3.175 (derived)
bend "Bend16" dims "d410" = 3.175 (derived), "d411" = 3.175 (derived), "d412" = 1.5875 (derived), "d413" = 6.35 (derived), "d414" = 3.175 (derived), "SeamGap" = 0.00508, "Thickness" = 3.175 (derived)
face "Plate18" dims "d427" = 3.175 (derived), "d428" = 3.175 (derived), "d430" = 6.35 (derived), "Thickness" = 3.175 (derived)
bend "Bend17" dims "d427" = 3.175 (derived), "d428" = 3.175 (derived), "d429" = 1.5875 (derived), "d430" = 6.35 (derived), "d431" = 3.175 (derived), "SeamGap" = 0.00508, "Thickness" = 3.175 (derived)
face "Plate19" dims "d552" = 3.175 (derived), "d553" = 3.175 (derived), "d555" = 6.35 (derived), "Thickness" = 3.175 (derived)
bend "Bend18" dims "d552" = 3.175 (derived), "d553" = 3.175 (derived), "d554" = 1.5875 (derived), "d555" = 6.35 (derived), "d556" = 3.175 (derived), "SeamGap" = 0.00508, "Thickness" = 3.175 (derived)
feature "쀀쀟"
other parameters: "KFactor" = 4.4, "BendRadius" = 3.175 (= Thickness), "BendReliefWidth" = 3.175 (= Thickness), "BendReliefDepth" = 1.5875 (= 0.5 x Thickness), "CornerReliefSize" = 12.7 (= 4 x Thickness), "MinimumRemnant" = 6.35 (= 2 x Thickness), "TransitionRadius" = 3.175 (= BendRadius), "JacobiRadiusSize" = 3.175 (= Thickness), "GapSize" = 3.175 (= Thickness), "d2" = 3.175 (= BendRadius)
